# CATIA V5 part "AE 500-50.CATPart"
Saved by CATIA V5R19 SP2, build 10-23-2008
Part number: AE 500-50
Bounding box of the stored display mesh (mm): x -22.494 to 22.494, y -22.494 to 22.494, z 0 to 150
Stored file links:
  C:\Users\Bora\Desktop\3D Katı model\AE serisi\AE 500\AE 500-50.CATPart
  C:\Program Files\Dassault Systemes\B19\intel_a\reffiles\standard\MetricThickPitch.txt
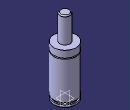
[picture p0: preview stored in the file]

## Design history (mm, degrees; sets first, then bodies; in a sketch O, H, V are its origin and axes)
Body1 (main body)
  Sketch1 on yz-plane, origin (0, 0, 0), H (0, 1, 0), V (0, 0, 1)
    point P1 (22.5, 83.5)
    point P8 (22.5, 85.5)
    point P9 (22.5, 85.5)
    point P10 (22.5, 83.5)
    point P11 (10, 148)
    point P13 (10, 148)
    line L1 (22.5, 83.5) -> (22.5, 8)
    line L2 (22.5, 4) -> (22.5, 0)
    line L3 (20, 8) -> (20, 4)
    line L4 (22.5, 99) -> (22.5, 85.5)
    arc A1 centre (22.5, 84.5) radius 1 from (22.5, 85.5) to (22.5, 83.5) ccw
    line L5 (10, 148) -> (10, 99)
    arc A2 centre (8, 148) radius 2 from (10, 148) to (8, 150) ccw
    line L6 (8, 150) -> (0, 150)
    point P15 (0, 150)
    line L7 (10, 99) -> (22.5, 99)
    line L8 (0, 0) -> (22.5, 0)
    line L9 (20, 8) -> (22.5, 8)
    line L10 (20, 4) -> (22.5, 4)
    coincidence: P15 V, P1 P10, P8 P9, P11 P13
    tangency: L6 A2
    horizontal: L7 H, L8 H, L9 H, L10 H
  Shaft1: profile Sketch1, axis Sketch1.V, angle 360
  Sketch2 on face of Shaft1 from Sketch1.L8, origin (0, 0, 0), H (1, 0, 0), V (0, -1, 0)
    point P1 (10, 0)
    distance P1 V = 10
  Hole1: placed by Sketch2, at (10, 0, 0) direction (0, 0, 1), diameter 6.647, depth 13, threaded "M8", thread diameter 8, thread depth 13, pitch 1.25
  CircPattern1: of Hole1, instances 2, angular step 180, axis from xy-plane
